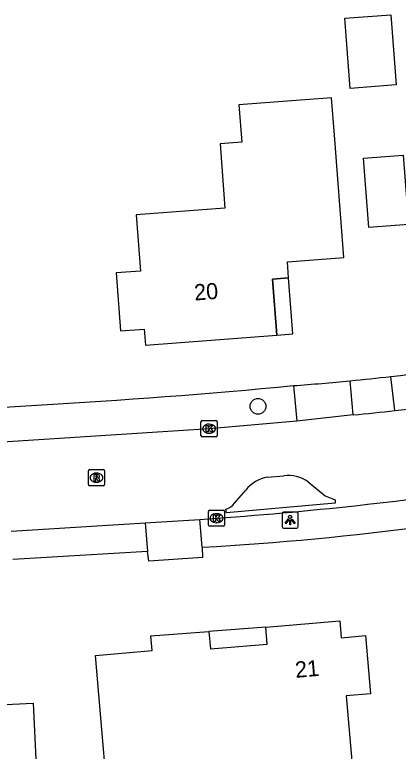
# Model space of a CAD drawing. Extents: x 162675 to 163482, y 379761 to 381227.
# Drawn here: x 163145.1 to 163168.84, y 380819.72 to 380865.33 of the extents above; entities that cross this region are included whole.
import ezdxf

# ---------------------------------------------------------------- set-up
doc = ezdxf.new("R2010")
doc.units = 0
for name, color, linetype in [('IMGEO_Boom', 7, 'Continuous'), ('IMGEO_Groenvoorziening', 7, 'Continuous'), ('IMGEO_Kolk', 7, 'Continuous'), ('IMGEO_Lichtpunt', 7, 'Continuous'), ('IMGEO_Pand', 7, 'Continuous'), ('IMGEO_Pand_nummerreeks', 7, 'Continuous'), ('IMGEO_Pand_overbouw', 7, 'Continuous'), ('IMGEO_Parkeervlak_halfverhard', 7, 'Continuous'), ('IMGEO_Rijbaan_lokaal_gesloten', 7, 'Continuous'), ('IMGEO_Rioolput', 7, 'Continuous'), ('IMGEO_Voetpad_open', 7, 'Continuous')]:
    doc.layers.add(name, color=color, linetype=linetype)

msp = doc.modelspace()

# ---------------------------------------------------------------- linework, layer by layer
at = {"layer": 'IMGEO_Boom'}
msp.add_circle((163160.156, 380841.08), 0.489, dxfattribs=at)
at = {"layer": 'IMGEO_Groenvoorziening'}
for centre, radius, start, end in [((163151.601, 380990.057), 148.081, 276.50679, 280.16179), ((163120.192, 381289.265), 448.884, 271.31965, 275.389)]:
    msp.add_arc(centre, radius, start, end, dxfattribs=at)
at = {"layer": 'IMGEO_Kolk'}
for p, q in [((163156.626, 380839.272), (163156.626, 380840.124)), ((163156.701, 380840.198), (163157.553, 380840.198)), ((163157.627, 380840.124), (163157.627, 380839.272)), ((163157.114, 380839.978), (163157.139, 380839.978)), ((163157.553, 380839.198), (163156.701, 380839.198)), ((163157.137, 380839.418), (163157.112, 380839.418)), ((163157.165, 380834.655), (163158.017, 380834.655)), ((163157.09, 380833.729), (163157.09, 380834.581)), ((163157.578, 380834.435), (163157.603, 380834.435)), ((163158.091, 380834.581), (163158.091, 380833.729)), ((163157.601, 380833.875), (163157.576, 380833.875)), ((163158.017, 380833.655), (163157.165, 380833.655))]:
    msp.add_line(p, q, dxfattribs=at)
for points in [[(163156.626, 380839.272), (163156.626, 380840.124)], [(163156.701, 380840.198), (163157.553, 380840.198)], [(163157.627, 380840.124), (163157.627, 380839.272)], [(163156.947, 380839.898), (163157.07, 380839.898), (163157.07, 380839.747), (163157.2, 380839.898), (163157.364, 380839.898), (163157.218, 380839.747), (163157.371, 380839.498), (163157.219, 380839.498), (163157.134, 380839.662), (163157.07, 380839.595), (163157.07, 380839.498), (163156.947, 380839.498), (163156.947, 380839.898)], [(163157.553, 380839.198), (163156.701, 380839.198)], [(163157.165, 380834.655), (163158.017, 380834.655)], [(163157.09, 380833.729), (163157.09, 380834.581)], [(163157.411, 380834.355), (163157.534, 380834.355), (163157.534, 380834.204), (163157.664, 380834.355), (163157.828, 380834.355), (163157.682, 380834.204), (163157.835, 380833.955), (163157.683, 380833.955), (163157.598, 380834.119), (163157.534, 380834.052), (163157.534, 380833.955), (163157.411, 380833.955), (163157.411, 380834.355)], [(163158.091, 380834.581), (163158.091, 380833.729)], [(163158.017, 380833.655), (163157.165, 380833.655)]]:
    msp.add_lwpolyline(points, dxfattribs=at)
for centre, start, end in [((163156.703, 380840.122), 91.552, 178.448), ((163156.703, 380840.122), 91.552, 178.448), ((163157.551, 380840.122), 1.552, 88.448), ((163157.551, 380840.122), 1.552, 88.448), ((163156.703, 380839.274), 181.552, 268.448), ((163156.703, 380839.274), 181.552, 268.448), ((163157.551, 380839.274), 271.552, 358.448), ((163157.551, 380839.274), 271.552, 358.448), ((163157.167, 380834.579), 91.552, 178.448), ((163157.167, 380834.579), 91.552, 178.448), ((163158.015, 380834.579), 1.552, 88.448), ((163158.015, 380834.579), 1.552, 88.448), ((163157.167, 380833.731), 181.552, 268.448), ((163157.167, 380833.731), 181.552, 268.448), ((163158.015, 380833.731), 271.552, 358.448), ((163158.015, 380833.731), 271.552, 358.448)]:
    msp.add_arc(centre, 0.0765, start, end, dxfattribs=at)
for centre, major_axis, ratio, start_param, end_param in [((163157.113, 380839.698), (-0.387, 0.002), 0.722429, 4.712389, 7.853982), ((163157.138, 380839.698), (-0.39, 0.002), 0.717154, 1.570796, 4.712389), ((163157.577, 380834.155), (-0.387, 0.002), 0.722429, 4.712389, 7.853982), ((163157.602, 380834.155), (-0.39, 0.002), 0.717154, 1.570796, 4.712389)]:
    msp.add_ellipse(centre, major_axis=major_axis, ratio=ratio, start_param=start_param, end_param=end_param, dxfattribs=at)
at = {"layer": 'IMGEO_Lichtpunt'}
for p, q in [((163161.646, 380834.443), (163161.646, 380833.636)), ((163161.646, 380834.443), (163161.646, 380833.636)), ((163162.548, 380834.538), (163161.74, 380834.538)), ((163162.548, 380834.538), (163161.74, 380834.538)), ((163162.642, 380833.636), (163162.642, 380834.443)), ((163162.642, 380833.636), (163162.642, 380834.443)), ((163161.74, 380833.542), (163162.548, 380833.542)), ((163161.74, 380833.542), (163162.548, 380833.542))]:
    msp.add_line(p, q, dxfattribs=at)
for points in [[(163162.02, 380834.107), (163162.059, 380834.079), (163161.871, 380833.817), (163161.833, 380833.844), (163162.02, 380834.107)], [(163162.122, 380834.059), (163162.169, 380834.059), (163162.169, 380833.737), (163162.122, 380833.737), (163162.122, 380834.059)], [(163162.232, 380834.079), (163162.27, 380834.106), (163162.457, 380833.844), (163162.418, 380833.816), (163162.232, 380834.079)]]:
    msp.add_lwpolyline(points, dxfattribs=at)
msp.add_circle((163162.145, 380834.241), 0.0994, dxfattribs=at)
for centre, start, end in [((163161.74, 380834.443), 90, 180), ((163161.74, 380834.443), 90, 180), ((163162.548, 380834.443), 0, 90), ((163162.548, 380834.443), 0, 90), ((163161.74, 380833.636), 180, 270), ((163161.74, 380833.636), 180, 270), ((163162.548, 380833.636), 270, 0), ((163162.548, 380833.636), 270, 360)]:
    msp.add_arc(centre, 0.0946, start, end, dxfattribs=at)
at = {"layer": 'IMGEO_Pand'}
for points in [[(163168.713, 380860.989), (163165.868, 380860.772), (163165.537, 380865.114), (163168.382, 380865.331), (163168.713, 380860.989)], [(163164.886, 380857.883), (163164.71, 380860.185), (163158.972, 380859.748), (163159.147, 380857.445), (163157.817, 380857.344), (163158.113, 380853.351), (163152.622, 380852.946), (163152.881, 380849.453), (163151.374, 380849.342), (163151.64, 380845.749), (163153.116, 380845.87), (163153.192, 380844.873), (163161.316, 380845.493), (163161.052, 380848.963), (163162.05, 380849.04), (163161.974, 380850.038), (163165.464, 380850.305), (163164.886, 380857.883)], [(163169.469, 380852.339), (163167.016, 380852.152), (163166.688, 380856.446), (163169.142, 380856.634), (163169.469, 380852.339)], [(163167.121, 380823.291), (163165.612, 380823.161), (163165.998, 380818.654), (163161.491, 380818.267), (163161.832, 380814.279), (163154.747, 380813.671), (163151.157, 380813.363), (163150.102, 380825.663), (163153.606, 380825.963), (163153.528, 380826.876), (163157.114, 380827.141), (163157.207, 380826.06), (163160.722, 380826.363), (163160.632, 380827.401), (163165.216, 380827.797), (163165.306, 380826.758), (163166.813, 380826.888), (163167.121, 380823.291)], [(163146.241, 380822.696), (163146.629, 380814.46), (163146.558, 380814.458), (163140.39, 380814.225), (163140.299, 380816.346), (163133.583, 380816.059), (163133.113, 380826.286), (163141.222, 380826.64), (163141.301, 380825.003), (163143.975, 380825.101), (163144.089, 380822.593), (163146.241, 380822.696)]]:
    msp.add_lwpolyline(points, dxfattribs=at)
at = {"layer": 'IMGEO_Pand_overbouw'}
for points in [[(163162.05, 380849.04), (163161.052, 380848.963), (163161.316, 380845.493), (163162.314, 380845.57)], [(163160.632, 380827.401), (163157.114, 380827.141), (163157.207, 380826.06), (163160.722, 380826.363)]]:
    msp.add_lwpolyline(points, close=True, dxfattribs=at)
at = {"layer": 'IMGEO_Parkeervlak_halfverhard'}
msp.add_lwpolyline([(163153.325, 380832.093), (163144.977, 380831.596)], dxfattribs=at)
msp.add_arc((163146.482, 381015.166), 183.09, 273.20212, 281.95764, dxfattribs=at)
at = {"layer": 'IMGEO_Rijbaan_lokaal_gesloten'}
for points in [[(163166.051, 380840.55), (163162.556, 380840.168)], [(163162.556, 380840.168), (163157.127, 380839.698), (163142.738, 380838.768)], [(163160.741, 380836.689), (163161.758, 380836.787)], [(163163.265, 380836.407), (163164.311, 380835.536)], [(163164.311, 380835.536), (163164.926, 380835.291), (163164.94, 380835.088), (163158.205, 380834.498), (163158.175, 380834.717)], [(163158.709, 380835.096), (163159.396, 380835.9)], [(163156.557, 380834.074), (163157.591, 380834.155)], [(163144.869, 380833.344), (163153.175, 380833.877)], [(163153.175, 380833.877), (163156.557, 380834.074)]]:
    msp.add_lwpolyline(points, dxfattribs=at)
for centre, radius, start, end in [((163153.856, 380968.233), 128.264, 276.61627, 280.93109), ((163153.741, 380969.376), 129.413, 275.45826, 276.60824), ((163161.089, 380834.555), 2.163, 99.2637, 141.5295), ((163162.022, 380834.654), 2.149, 54.6514, 97.0436), ((163140.716, 381068.487), 234.939, 274.11905, 278.69294), ((163157.978, 380835.561), 0.867, 283.1675, 327.562)]:
    msp.add_arc(centre, radius, start, end, dxfattribs=at)
at = {"layer": 'IMGEO_Rioolput'}
for p, q in [((163149.657, 380836.239), (163149.657, 380837.091)), ((163149.732, 380837.165), (163150.584, 380837.165)), ((163150.145, 380836.945), (163150.17, 380836.945)), ((163150.658, 380837.091), (163150.658, 380836.239)), ((163150.584, 380836.165), (163149.732, 380836.165)), ((163150.168, 380836.385), (163150.143, 380836.385))]:
    msp.add_line(p, q, dxfattribs=at)
for points in [[(163149.657, 380836.239), (163149.657, 380837.091)], [(163149.732, 380837.165), (163150.584, 380837.165)], [(163150.658, 380837.091), (163150.658, 380836.239)], [(163150.246, 380836.863), (163149.994, 380836.865), (163149.994, 380836.465)], [(163149.994, 380836.465), (163150.118, 380836.465), (163150.118, 380836.627), (163150.129, 380836.627)], [(163150.172, 380836.784), (163150.118, 380836.784), (163150.118, 380836.703)], [(163150.118, 380836.703), (163150.17, 380836.703)], [(163150.176, 380836.598), (163150.247, 380836.465), (163150.387, 380836.465), (163150.322, 380836.591)], [(163150.584, 380836.165), (163149.732, 380836.165)]]:
    msp.add_lwpolyline(points, dxfattribs=at)
for centre, radius, start, end in [((163149.734, 380837.089), 0.0765, 91.552, 178.448), ((163149.734, 380837.089), 0.0765, 91.552, 178.448), ((163150.582, 380837.089), 0.0765, 1.552, 88.448), ((163150.582, 380837.089), 0.0765, 1.552, 88.448), ((163150.128, 380836.574), 0.0533, 26.0293, 88.6989), ((163150.154, 380836.892), 0.19, 274.7715, 282.9687), ((163150.178, 380836.688), 0.0964, 77.0061, 93.1865), ((163150.192, 380836.745), 0.0378, 276.6634, 79.6772), ((163150.245, 380836.753), 0.109, 350.3612, 89.416), ((163150.243, 380836.753), 0.112, 277.5842, 350.9817), ((163150.227, 380836.538), 0.108, 29.5134, 73.7905), ((163149.734, 380836.241), 0.0765, 181.552, 268.448), ((163149.734, 380836.241), 0.0765, 181.552, 268.448), ((163150.582, 380836.241), 0.0765, 271.552, 358.448), ((163150.582, 380836.241), 0.0765, 271.552, 358.448)]:
    msp.add_arc(centre, radius, start, end, dxfattribs=at)
for centre, major_axis, ratio, start_param, end_param in [((163150.144, 380836.665), (-0.387, 0.002), 0.722429, 4.712389, 7.853982), ((163150.169, 380836.665), (-0.39, 0.002), 0.717154, 1.570796, 4.712389)]:
    msp.add_ellipse(centre, major_axis=major_axis, ratio=ratio, start_param=start_param, end_param=end_param, dxfattribs=at)
at = {"layer": 'IMGEO_Voetpad_open'}
for points in [[(163168.634, 380840.823), (163168.382, 380842.93)], [(163162.35, 380842.365), (163162.556, 380840.168)], [(163166.051, 380840.55), (163165.852, 380842.663)], [(163153.175, 380833.877), (163153.325, 380832.093)], [(163156.709, 380832.362), (163156.557, 380834.074)], [(163156.709, 380832.362), (163156.73, 380831.724), (163153.391, 380831.49), (163153.325, 380832.093)]]:
    msp.add_lwpolyline(points, dxfattribs=at)
for centre, radius, start, end in [((163151.886, 380987.12), 145.13, 275.52214, 276.52652), ((163151.073, 380995.616), 153.666, 274.20857, 275.51908)]:
    msp.add_arc(centre, radius, start, end, dxfattribs=at)

# ---------------------------------------------------------------- texts
at = {"layer": 'IMGEO_Pand_nummerreeks'}
for s, rotation, p in [('20', 4.3659, (163156.241, 380847.632)), ('21', 4.916, (163162.495, 380824.269))]:
    msp.add_text(s, height=1, rotation=rotation, dxfattribs=at).set_placement(p)

doc.saveas('drawing.dxf')
